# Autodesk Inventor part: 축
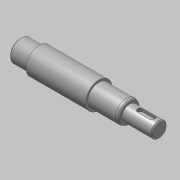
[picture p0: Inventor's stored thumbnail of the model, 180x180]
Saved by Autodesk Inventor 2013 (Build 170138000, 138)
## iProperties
Created: 2016-06
Part Number: 축
Material: 강철, 연강
Document SubType Name: Modeling
Designer: mduedu
Density: 7.86 g/cm^3
Author: mduedu
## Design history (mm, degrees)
sketch "스케치1"
  geometry: L1 (-63, 0)-(63, 0); L2 (-63, 0)-(-63, 10); L3 (-63, 10)-(-46, 10); L4 (-46, 10)-(-46, 12); L5 (-46, 12)-(8, 12); L6 (8, 12)-(8, 10); L7 (8, 10)-(36, 10); L8 (36, 10)-(36, 7); L9 (36, 7)-(63, 7); L10 (63, 7)-(63, 0); 2 further points
  constraints: 20 end point, 5 parallel, 2 perpendicular, 1 coincident, 1 collinear, 1 horizontal, 1 midpoint, 1 vertical
  dimensions: "d0" = 126 distance of L1.start L1.end; "d2" = 14 diameter of L9 L1; "d3" = 20 diameter of L7 L1; "d4" = 24 diameter of L5 L1; "d5" = 20 diameter of L3 L1; "d6" = 17 distance of L2.end L3.end; "d7" = 27 distance of L8.end L9.end; "d8" = 55 distance from line of L5.end L10
revolve "회전1" sketch "스케치1" stored, may be unused: angle "d9" = 90 deg
sketch "스케치5"
  geometry: L1 (63, 10)-(63, -10) reference; L2 (63, -10)-(46, -10) reference; L3 (46, -10)-(46, -12) reference; L4 (46, -12)-(-8, -12) reference; L5 (-8, -12)-(-8, -10) reference; L6 (-8, -10)-(-36, -10) reference; L7 (-36, -10)-(-36, -7) reference; L8 (-36, -7)-(-63, -7) reference; L9 (-63, -7)-(-63, 7) reference; L10 (-63, 7)-(-36, 7) reference; L11 (-36, 7)-(-36, 10) reference; L12 (-36, 10)-(-8, 10) reference; L13 (-8, 10)-(-8, 12) reference; L14 (-8, 12)-(46, 12) reference; L15 (46, 12)-(46, 10) reference; L16 (46, 10)-(63, 10) reference; L17 (-63, 0)-(63, 0); L18 (-36, 8.85)-(-34.008, 10); L19 (-34.008, 10)-(-36, 10); L20 (-36, 10)-(-36, 8.85); 1 further point
  constraints: 8 end point, 2 midpoint, 2 point on line, 1 collinear, 1 perpendicular
  dimensions: "d36" = 17.7 diameter of L18.start L17; "d37" = 30 deg angle of L12 L18
revolve "회전3" sketch "스케치5" stored, may be unused: angle "d38" = 90 deg
fillet "모깎기1" dims "d13" = 4, "d39" = 0.5
node "작업 평면1"
sketch "스케치2"
  geometry: L1 (-4, 2.5)-(7, 2.5); L2 (7, -2.5)-(-4, -2.5); L3 (-4, 0)-(7, 0); L4 (-13.5, 8.561)-(-13.5, -8.561) reference; A1 r 2.5 centre (-4, 0) between (-4, 2.5) and (-4, -2.5); A2 r 2.5 centre (7, 0) between (7, -2.5) and (7, 2.5); 1 further point
  constraints: 6 end point, 4 point on circle, 3 tangent, 2 centre point, 2 parallel, 1 horizontal, 1 horizontal alignment
  dimensions: "d15" = 5 distance between parallel lines of L2 L1; "d16" = 16 dimension on A2 A1; "d40" = 7 distance edge to line of A1 L4
extrude "돌출1" cut sketch "스케치2" distance "d17" = 3; taper "d18" = 0 deg
chamfer "모따기2" distance "d19" = 1; stored, may be unused: second distance "d20" = 2, angle "d21" = 30 deg
sketch "스케치3"
  geometry: L1 (-36, -7)-(-62, -7) reference; L2 (-63, -6)-(-63, 6) reference; L3 (-39.5, -7)-(-41, -5.5); L4 (-41, -5.5)-(-41, -7); L5 (-39.5, -7)-(-41, -7); 1 further point
  constraints: 6 end point, 2 point on line, 1 collinear, 1 vertical
  dimensions: "d22" = 45 deg angle of L4 L3; "d23" = 22 distance between parallel lines of L2 L4; "d24" = 3 diameter of L3.start L4
revolve "회전2" stored, may be unused: angle "d25" = 90 deg
node "작업점1"
sketch "스케치4"
  geometry: 1 further point
hole "구멍1" sketch "스케치4" at (0, 0) diameter "d26" = 3.242; stored, may be unused: countersink angle "d30" = 90 deg, drill point angle "d32" = 120 deg; dims "d27" = 8, "d28" = 4, "d29" = 2, "d31" = 11
chamfer "모따기3" distance "d33" = 2; stored, may be unused: second distance "d34" = 2, angle "d35" = 30 deg
node "솔리드1"
node "절단 모서리 투영1"
